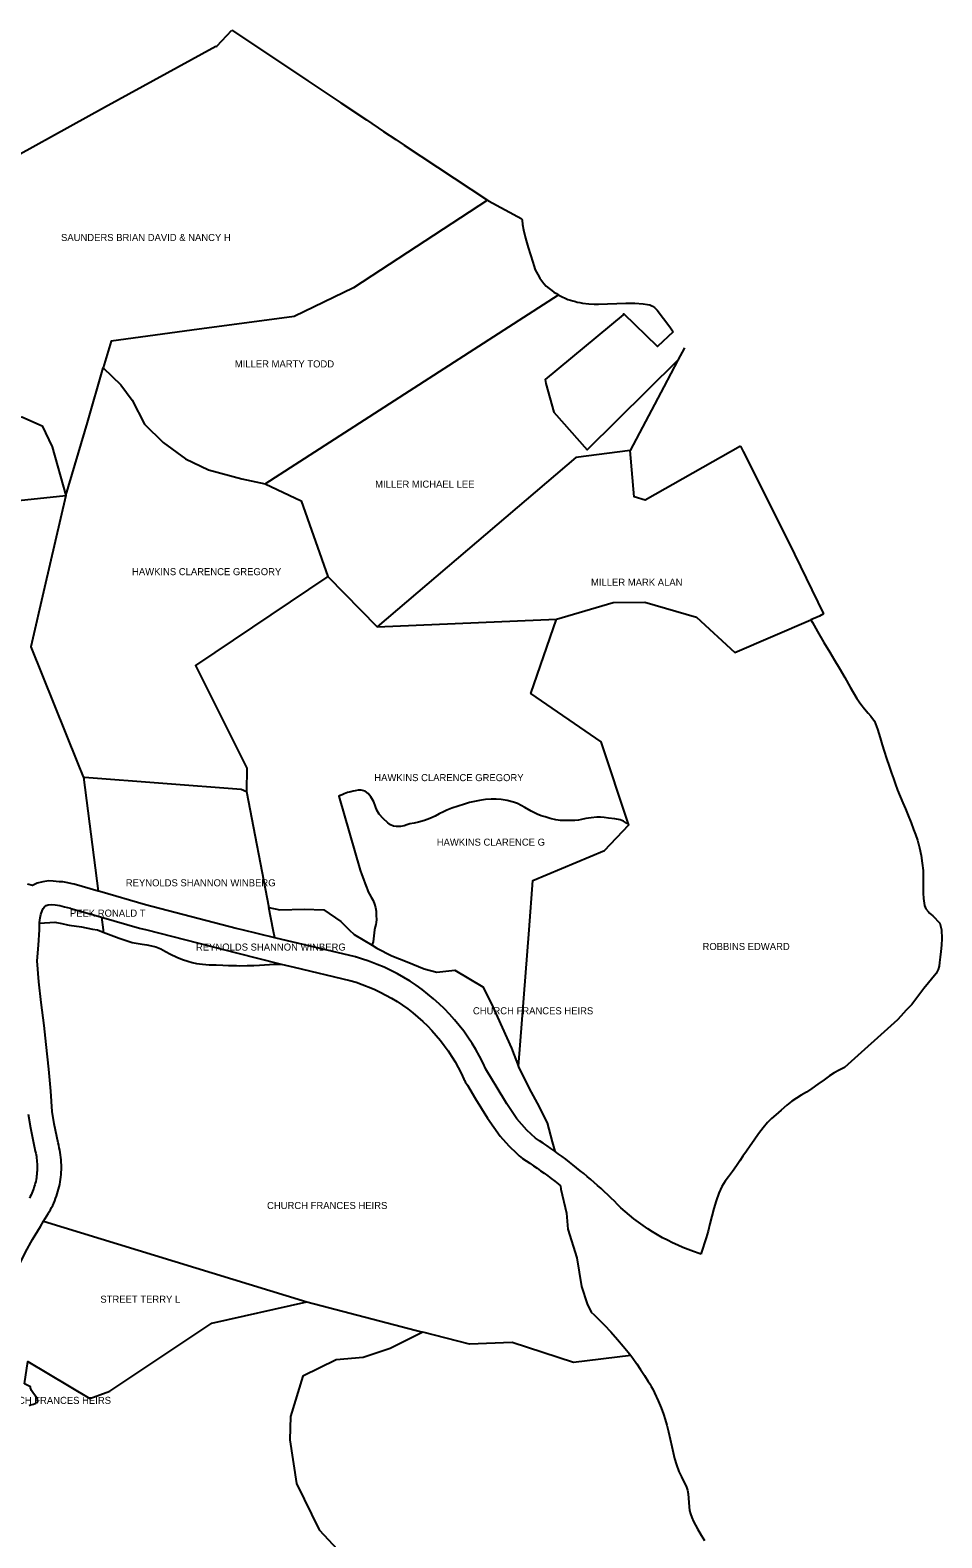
# Model space of a CAD drawing. Extents: x 1249333 to 1254314, y 856599 to 862241.
# Drawn here: x 1252043 to 1254314, y 858486 to 862241 of the extents above; entities that cross this region are included whole.
import ezdxf

# ---------------------------------------------------------------- set-up
doc = ezdxf.new("R2010")
doc.units = 0
doc.layers.add('Old_Level_12', color=7, linetype='Continuous')
doc.layers.add('Old_Level_32', color=7, linetype='Continuous')

msp = doc.modelspace()

# ---------------------------------------------------------------- linework, layer by layer
at = {"layer": 'Old_Level_12'}
for p, q in [((1252545.5, 862241), (1252649, 862172)), ((1252649, 862172), (1252734.875, 862114.813)), ((1252734.875, 862114.813), (1252817.375, 862059.75)), ((1252817.375, 862059.75), (1252881.125, 862017.25)), ((1252628.5, 861110.625), (1253359, 861581.875)), ((1253673, 861449.875), (1253656.75, 861419.125)), ((1253656.75, 861419.125), (1253621.625, 861352.813)), ((1253621.625, 861352.813), (1253537.5, 861193.938)), ((1253812.375, 861204.75), (1253819, 861191.938)), ((1252785, 860880.313), (1252907.625, 860755.063)), ((1252907.625, 860755.063), (1253354.25, 860774.188)), ((1252175.875, 860380.625), (1252212.25, 860096.5)), ((1252582.5, 860344.5), (1252638, 860056)), ((1252664.875, 859915.563), (1252668.5, 859914.625)), ((1254203.25, 859775.813), (1254071.75, 859657.25)), ((1252076.875, 859274.438), (1252732, 859073.375)), ((1252732, 859073.375), (1253021.75, 858998.313))]:
    msp.add_line(p, q, dxfattribs=at)
for points in [[(1252506.125, 862199.875), (1252508.625, 862201.188), (1252545.5, 862241)], [(1252506.125, 862199.875), (1252228.75, 862048.438), (1251924.5, 861880.5), (1251772.125, 861797.75), (1251710.5, 861821.313), (1251641, 861821.313)], [(1252881.125, 862017.25), (1252923.75, 861988.875), (1252954.25, 861968.625)], [(1252954.25, 861968.625), (1252975.25, 861954.75), (1253182.125, 861817.813)], [(1251641, 861821.313), (1251574.25, 861769.375), (1251555.375, 861709.75), (1251720.125, 861462.25), (1251852.5, 861261.125), (1251911.625, 861274.75), (1252022.875, 861277.5), (1252073.25, 861255.125), (1252098, 861203.188), (1252131.875, 861081.875)], [(1253182.125, 861817.813), (1252848.5, 861599), (1252701, 861527.438), (1252446.25, 861493.438), (1252244.75, 861466.688), (1252225.5, 861399.938)], [(1253182.125, 861817.813), (1253185.25, 861815.75), (1253268.25, 861771.188)], [(1253268.25, 861771.188), (1253268.375, 861767.563), (1253269.375, 861757.188), (1253271.875, 861743.625), (1253276.875, 861722.5), (1253283.375, 861699.875), (1253295.25, 861662.938), (1253297.75, 861654.438), (1253301.5, 861643.75), (1253307.375, 861632.188), (1253313, 861623.25), (1253317.875, 861616.313), (1253322.375, 861610.125), (1253328.625, 861603.563), (1253336, 861597.563), (1253342.375, 861592.563), (1253348, 861588.5), (1253354, 861584.75), (1253359, 861581.875)], [(1253359, 861581.875), (1253360.375, 861581.063), (1253368.25, 861577), (1253375.5, 861573.563), (1253382.625, 861570.5), (1253389, 861568.438), (1253395.25, 861566.688), (1253401.25, 861565.125), (1253406, 861563.875), (1253412, 861562.5), (1253419.375, 861561.25), (1253435, 861559.563), (1253447.875, 861558.688), (1253459, 861558.188), (1253526.875, 861560.938), (1253549.5, 861560.938), (1253570, 861559.25), (1253581.25, 861557.438), (1253586.375, 861556.5), (1253593.625, 861553.188), (1253598.5, 861549.875), (1253604.875, 861543.75), (1253636.375, 861501.813), (1253644.875, 861489.688)], [(1253644.875, 861489.688), (1253605.625, 861453.125), (1253521.625, 861534.75), (1253520, 861532.313), (1253326.375, 861371.125), (1253327.875, 861361.125), (1253347.875, 861289.5), (1253430.375, 861195.5), (1253656.75, 861419.125)], [(1252131.875, 861081.875), (1252186.375, 861263.938), (1252225.5, 861399.938)], [(1252225.5, 861399.938), (1252269.25, 861357.875), (1252297, 861319.125), (1252328.375, 861260), (1252374.5, 861213.875), (1252429.875, 861173.25), (1252487.125, 861145.563), (1252570.25, 861123.375), (1252628.5, 861110.625)], [(1253537.5, 861193.938), (1253402.75, 861176.375), (1252907.625, 860755.063)], [(1253812.375, 861204.75), (1253575.125, 861070.063), (1253547.875, 861078.375), (1253537.5, 861193.938)], [(1253819, 861191.938), (1253933.375, 860964.875), (1254019.25, 860787.188)], [(1252628.5, 861110.625), (1252718.125, 861068.375), (1252785, 860880.313)], [(1251142.625, 860976.438), (1251233.125, 860988.438), (1251635.75, 861029.625), (1252131.875, 861081.875)], [(1252131.875, 861081.875), (1252078.875, 860852.5), (1252044.875, 860704.938), (1252160.75, 860415.813), (1252175.5, 860381.25), (1252175.875, 860380.625)], [(1252785, 860880.313), (1252455.125, 860658.813), (1252582.875, 860402.5), (1252582.5, 860344.5)], [(1253354.25, 860774.188), (1253495.125, 860815.063), (1253574.5, 860816.5), (1253703.25, 860779.313)], [(1253533.625, 860263.25), (1253465.125, 860468.25), (1253290, 860589), (1253354.25, 860774.188)], [(1253703.25, 860779.313), (1253798.625, 860691), (1253987.75, 860772.438)], [(1254019.25, 860787.188), (1254009.25, 860781.688), (1253987.75, 860772.438)], [(1253987.75, 860772.438), (1253991.625, 860765.25), (1254004.5, 860742.938), (1254020.375, 860716.125), (1254035.125, 860691.438), (1254046.875, 860672.125), (1254058.25, 860653.125), (1254072.25, 860628.813), (1254086.125, 860604.188), (1254094, 860590.25), (1254102.25, 860576.75), (1254112.5, 860562.188), (1254121.875, 860550.25), (1254130.625, 860539.875), (1254137.625, 860532.625), (1254146.125, 860519.5), (1254153.875, 860499.563), (1254160.5, 860478.25), (1254165.375, 860461.125), (1254170.25, 860444.813), (1254176, 860426.625), (1254182.75, 860407.438), (1254188.875, 860390.25), (1254193.625, 860377.063), (1254198, 860364.563), (1254203.875, 860348.438), (1254210.375, 860331.875), (1254216.875, 860316.5), (1254223.375, 860301.75), (1254230.375, 860285.125), (1254237.5, 860266.875), (1254243.75, 860250.438), (1254248.75, 860237.5), (1254253.5, 860223.125), (1254255.125, 860216.938), (1254255.875, 860214.125)], [(1252175.875, 860380.625), (1252178.625, 860380.5), (1252568.75, 860350.688), (1252582.5, 860344.5)], [(1253533.625, 860263.25), (1253529, 860265.875), (1253521.5, 860270.688), (1253513.25, 860273.938), (1253499.625, 860276.375), (1253483.5, 860278.313), (1253472.75, 860279.625), (1253463.75, 860280.5), (1253454.75, 860280.688), (1253441, 860279.375), (1253427.375, 860277.063), (1253416.75, 860274.688), (1253409.375, 860273.438), (1253399.75, 860272.688), (1253388.75, 860272.313), (1253375.75, 860272.188), (1253364.375, 860272.625), (1253352.75, 860274.313), (1253338.875, 860277.75), (1253325.75, 860281.625), (1253316.375, 860284.313), (1253305.75, 860288.563), (1253291.125, 860296.125), (1253275.625, 860304.688), (1253265.875, 860310.063), (1253256.75, 860314.625), (1253247.125, 860318.313), (1253231.75, 860322.063), (1253216.375, 860324.438), (1253203.625, 860325.875), (1253191.75, 860326), (1253177.25, 860324.563), (1253162.375, 860322.313), (1253149.75, 860319.875), (1253137.75, 860317), (1253125.25, 860313.5), (1253109.125, 860308.438), (1253093.625, 860303.063), (1253081.25, 860298.313), (1253072.625, 860294.313), (1253062.375, 860289), (1253052, 860283.5), (1253038.875, 860277.25), (1253025.375, 860272.188), (1253010.5, 860268.313), (1252999.5, 860266.188), (1252989.125, 860264.063), (1252981.25, 860261.5), (1252974.5, 860259.063), (1252965.5, 860257.375), (1252956.125, 860257.125), (1252948.125, 860258.75), (1252941, 860262), (1252934.125, 860266.688), (1252922.5, 860277.063), (1252912.75, 860288.438), (1252906.875, 860298.313), (1252903.625, 860307.5), (1252898.875, 860319.125), (1252892.125, 860331.063), (1252885.25, 860339.563), (1252877.375, 860345.563), (1252867.75, 860348.25), (1252860.125, 860347.875), (1252853, 860346.563), (1252847.75, 860345.5), (1252841.875, 860344.188), (1252833.875, 860341.813), (1252825, 860338.688), (1252820.125, 860336.688), (1252815.75, 860334.875), (1252811.75, 860333.063), (1252864.875, 860148.75), (1252869.5, 860137), (1252873.25, 860126.5), (1252877.75, 860114.375), (1252880.75, 860106.375), (1252883.375, 860099.438), (1252885.375, 860094.75), (1252888.375, 860089.313), (1252892.875, 860081.563), (1252897.375, 860073.188), (1252901.125, 860064.5), (1252903.625, 860056), (1252904.875, 860046.375), (1252905.5, 860035.875), (1252905.625, 860026.313), (1252905.25, 860018.813), (1252904.375, 860013.75), (1252902.875, 860007.25), (1252901.25, 860000.375), (1252897.625, 859970.188), (1252895.5, 859963.625), (1252894.875, 859961.75)], [(1253259.625, 859659.375), (1253286.375, 860000), (1253295.625, 860123.188), (1253474.25, 860197.938), (1253534.25, 860261.5), (1253533.625, 860263.25)], [(1254255.875, 860214.125), (1254258.25, 860204.5), (1254262.375, 860185.125), (1254265.5, 860166.125), (1254267.25, 860147.625), (1254268, 860126.75), (1254267.75, 860108.125), (1254267.5, 860091.375), (1254268.375, 860078), (1254270.75, 860060.938), (1254274.5, 860052.688), (1254280.75, 860044.875), (1254283.75, 860042.063)], [(1252212.25, 860096.5), (1252153, 860113.625), (1252148, 860114.813), (1252137.25, 860117.313), (1252124.5, 860119.438), (1252115.625, 860120), (1252100.25, 860121.563), (1252089.375, 860121.875), (1252075.125, 860120.125), (1252060.875, 860116.25), (1252049.375, 860110.813), (1252036.625, 860114.063)], [(1252652.375, 859980.625), (1252571.5, 860000), (1252556.75, 860003.813), (1252330.625, 860062.25), (1252216.375, 860095.313), (1252212.25, 860096.5)], [(1252066.625, 860016.75), (1252066.625, 860018.375), (1252067.125, 860024.5), (1252068.125, 860030.438), (1252069.75, 860038.375), (1252072.75, 860047.313), (1252075.5, 860053.625), (1252078.875, 860057.375), (1252083.125, 860060.5), (1252088.125, 860062.063), (1252096.625, 860063.125), (1252105.125, 860062.625), (1252117, 860060.5), (1252129, 860057.375), (1252143.5, 860053.938), (1252144.75, 860053.625), (1252212.875, 860033.875), (1252220.625, 860031.625)], [(1252220.625, 860031.625), (1252224.75, 860000), (1252225.375, 859994.375)], [(1252220.625, 860031.625), (1252315.625, 860004.125), (1252333.875, 860000), (1252556.875, 859943.063), (1252664.875, 859915.563)], [(1252652.375, 859980.625), (1252648.75, 860000), (1252638, 860056)], [(1252638, 860056), (1252665.25, 860049.688), (1252726, 860051.875), (1252774.875, 860050.125), (1252816.75, 860021.125), (1252838.25, 860000), (1252850.25, 859988.188), (1252894.875, 859961.75)], [(1254283.75, 860042.063), (1254291.625, 860034.688), (1254309.25, 860016.75), (1254313.25, 860000), (1254314.125, 859978.313), (1254313.5, 859961.75), (1254312, 859946.5), (1254310, 859931.75), (1254308.125, 859918.875), (1254307.125, 859909.375), (1254305, 859901.313), (1254299.875, 859891), (1254269.25, 859853.688), (1254239.5, 859814.188), (1254225.625, 859799.688), (1254211.625, 859784.875), (1254203.25, 859775.813)], [(1252076.875, 859274.438), (1252089, 859294.875), (1252090.75, 859297.688), (1252093.75, 859303), (1252096.625, 859308.438), (1252099.375, 859313.938), (1252102, 859319.5), (1252104.375, 859325.125), (1252106.625, 859330.813), (1252108.75, 859336.563), (1252110.75, 859342.375), (1252112.5, 859348.25), (1252114.125, 859354.188), (1252115.625, 859360.125), (1252116.875, 859366.125), (1252118, 859372.188), (1252119, 859378.25), (1252119.75, 859384.313), (1252120.375, 859390.438), (1252120.75, 859396.563), (1252121, 859402.688), (1252121.125, 859408.813), (1252121, 859414.938), (1252120.75, 859421.063), (1252120.375, 859427.188), (1252119.75, 859433.313), (1252119, 859439.375), (1252118.125, 859445.438), (1252117, 859451.5), (1252115.75, 859457.5), (1252114.25, 859463.438), (1252112.625, 859469.375), (1252102.75, 859517.375), (1252098.375, 859547.563), (1252094.375, 859598.25), (1252089.625, 859653.188), (1252082.75, 859714.188), (1252077.875, 859761.563), (1252070.625, 859819), (1252064.75, 859870.563), (1252061, 859922.625), (1252063.625, 859961.938), (1252066.875, 860000), (1252066.75, 860012.063), (1252066.625, 860016.75)], [(1252066.625, 860016.75), (1252104.75, 860019.125), (1252121.75, 860015.813), (1252136.25, 860012.438), (1252140.375, 860011.875), (1252171.5, 860007.438), (1252198.625, 860002.125), (1252211, 860000), (1252225.375, 859994.375)], [(1252225.375, 859994.375), (1252264.875, 859979), (1252282.25, 859973.25), (1252297.5, 859968.813), (1252312.125, 859965.75), (1252322.375, 859964.313), (1252333.75, 859962.688), (1252345.5, 859960.625), (1252356.5, 859957.75), (1252368.875, 859952.688), (1252380.5, 859946.375), (1252393.125, 859939.375), (1252408.5, 859932.188), (1252422.875, 859926.5), (1252435.625, 859922), (1252447, 859918.625), (1252457.625, 859916.188), (1252472.25, 859914.25), (1252488.875, 859913.25), (1252506.25, 859912.625), (1252522.875, 859912.188), (1252537, 859911.625), (1252550.75, 859911.063), (1252557, 859910.938)], [(1253350, 859448.5), (1253340.125, 859455.5), (1253330.75, 859462), (1253321.25, 859468.438), (1253311.75, 859474.813), (1253302.125, 859481.063), (1253280.625, 859501.063), (1253255.75, 859529.625), (1253230.75, 859566.688), (1253204, 859610.563), (1253194.875, 859625.563), (1253178.5, 859652.813), (1253170.75, 859669.438), (1253162.375, 859685.75), (1253153.375, 859701.75), (1253143.875, 859717.438), (1253133.75, 859732.75), (1253123.125, 859747.688), (1253111.875, 859762.25), (1253100.125, 859776.375), (1253087.875, 859790.063), (1253075.125, 859803.313), (1253061.875, 859816.063), (1253048.25, 859828.313), (1253034.125, 859840.063), (1253019.625, 859851.313), (1253004.75, 859862), (1252989.5, 859872.125), (1252973.875, 859881.688), (1252957.875, 859890.688), (1252941.5, 859899.125), (1252924.875, 859906.938), (1252908, 859914.125), (1252890.875, 859920.688), (1252881.75, 859923.813), (1252873.5, 859926.625), (1252855.875, 859931.938), (1252855.375, 859932.125), (1252853.375, 859932.563), (1252652.375, 859980.625)], [(1252894.875, 859961.75), (1252906.625, 859954.813), (1252943.75, 859935.5), (1252982.125, 859920.563), (1253024.375, 859902.813), (1253056, 859895.063), (1253101.25, 859899.75), (1253170.75, 859858.25), (1253191.75, 859817.375), (1253218.75, 859757.25), (1253242.25, 859705.125), (1253259.625, 859659.375)], [(1252557, 859910.938), (1252565.875, 859910.75), (1252583.625, 859911), (1252600.25, 859911.625), (1252614.375, 859912.375), (1252627.125, 859913.25), (1252639.625, 859914.188), (1252651.25, 859914.813), (1252663.625, 859914.938), (1252665, 859914.875), (1252668.5, 859914.625)], [(1252668.5, 859914.625), (1252701.25, 859906.875), (1252839.625, 859874.188), (1252855.125, 859869.5), (1252870.375, 859864.25), (1252881.125, 859860.125), (1252885.5, 859858.438), (1252900.375, 859852.125), (1252915, 859845.25), (1252929.375, 859837.813), (1252943.5, 859829.875), (1252957.25, 859821.438), (1252970.75, 859812.5), (1252983.875, 859803.063), (1252996.625, 859793.188), (1253009, 859782.813), (1253021, 859772), (1253032.625, 859760.75), (1253043.875, 859749.125), (1253054.625, 859737.063), (1253065, 859724.625), (1253074.875, 859711.813), (1253084.25, 859698.688), (1253093.125, 859685.188), (1253101.5, 859671.375), (1253109.375, 859657.25), (1253116.75, 859642.875), (1253123.625, 859628.25), (1253125, 859625.313), (1253127.125, 859621.813), (1253132.375, 859613.188), (1253152.75, 859579.438), (1253182, 859531.313), (1253214.125, 859485.875), (1253235.625, 859462.063), (1253255.625, 859443.313), (1253261.5, 859437.563), (1253269.625, 859430.688), (1253278.75, 859424.75), (1253287.875, 859418.688), (1253296.875, 859412.563), (1253305.875, 859406.375), (1253314.75, 859400.063), (1253323.625, 859393.688), (1253332.375, 859387.25), (1253341.125, 859380.75), (1253349.75, 859374.125), (1253358.375, 859367.438), (1253364, 859362.938)], [(1253259.625, 859659.375), (1253259.625, 859658.75), (1253285.875, 859604.938), (1253306.25, 859568.438), (1253331.25, 859519.125), (1253343.5, 859472.25), (1253350, 859448.5)], [(1254071.75, 859657.25), (1254058.5, 859650.563), (1254045.625, 859643.813), (1254034.375, 859636.563), (1254020.75, 859626.688), (1254005.625, 859615.625), (1253990, 859604.563), (1253976.75, 859596), (1253964, 859588.125), (1253951.875, 859580.688), (1253940.75, 859573.375), (1253927.625, 859563.313), (1253913.625, 859551.375), (1253900.5, 859539.625), (1253890, 859530.188), (1253880.25, 859520.25), (1253869.25, 859507.063), (1253857.75, 859491.938), (1253846.375, 859476.188), (1253836.5, 859462.313), (1253827.375, 859449), (1253818.75, 859436.375), (1253810.75, 859424.625), (1253802.25, 859412.188), (1253792.625, 859398.5), (1253783, 859385.25), (1253774.75, 859374.188), (1253766.5, 859360.813), (1253759, 859344.188), (1253752.25, 859325.5), (1253746.375, 859306.188), (1253741.125, 859286.75), (1253736.5, 859268.063), (1253731.75, 859250), (1253726.75, 859232.625), (1253722.875, 859220.375), (1253718.625, 859207.25), (1253715, 859194.688), (1253714.5, 859192.75)], [(1252038.625, 859540.813), (1252043.75, 859507), (1252053.875, 859457.375), (1252054.5, 859454), (1252054.875, 859452.813), (1252056, 859448.5), (1252057, 859444.188), (1252057.875, 859439.813), (1252058.625, 859435.438), (1252059.25, 859431.063), (1252059.75, 859426.625), (1252060.125, 859422.188), (1252060.375, 859417.75), (1252060.5, 859413.313), (1252060.5, 859404.438), (1252060.375, 859400), (1252060.125, 859395.563), (1252059.75, 859391.125), (1252059.25, 859386.688), (1252058.625, 859382.313), (1252057.875, 859377.938), (1252057, 859373.563), (1252056, 859369.25), (1252054.875, 859364.938), (1252053.625, 859360.688), (1252052.25, 859356.438), (1252050.75, 859352.25), (1252049.125, 859348.125), (1252047.375, 859344), (1252045.5, 859339.938), (1252043.5, 859335.938), (1252041.375, 859332)], [(1253714.5, 859192.75), (1253709.25, 859194.375), (1253695.75, 859198.875), (1253682.375, 859203.75), (1253669.125, 859209), (1253656.125, 859214.563), (1253643.25, 859220.5), (1253630.5, 859226.813), (1253618, 859233.438), (1253605.625, 859240.438), (1253593.5, 859247.75), (1253581.5, 859255.375), (1253569.75, 859263.375), (1253558.25, 859271.688), (1253547, 859280.313), (1253536, 859289.25), (1253525.25, 859298.438), (1253514.75, 859307.938), (1253506.625, 859316.063), (1253498.5, 859324.125), (1253490.25, 859332.063), (1253482, 859339.938), (1253473.625, 859347.75), (1253465.25, 859355.5), (1253456.75, 859363.188), (1253448.125, 859370.75), (1253439.5, 859378.25), (1253430.75, 859385.688), (1253422, 859393.063), (1253413.125, 859400.313), (1253404.25, 859407.5), (1253395.25, 859414.625), (1253386.25, 859421.625), (1253377.125, 859428.563), (1253368, 859435.438), (1253358.75, 859442.188), (1253350, 859448.5)], [(1253364, 859362.938), (1253365.125, 859354.563), (1253379.375, 859294.563), (1253382.375, 859254.688), (1253405.125, 859183.125), (1253416.5, 859111.75), (1253430.875, 859068.875), (1253440.25, 859048.125), (1253448.375, 859040.938), (1253460.875, 859029.188), (1253474.125, 859015.688), (1253489.25, 858999), (1253506.25, 858979.563), (1253520.75, 858962.938), (1253533.125, 858948), (1253539.25, 858940.125)], [(1251864.75, 858925.188), (1251873, 858939.75), (1251930.125, 859012.125), (1251968.875, 859075.25), (1251991.375, 859115.063), (1252031.875, 859197), (1252049.25, 859229.188), (1252068.875, 859261.063), (1252076.875, 859274.438)], [(1252028.875, 858869.563), (1252037.125, 858924.688), (1252192.25, 858832.625), (1252241.625, 858851.188), (1252496.125, 859020.25), (1252732, 859073.375)], [(1253021.75, 858998.313), (1252940, 858957.438), (1252872.875, 858935), (1252805.625, 858929), (1252722.375, 858888.5), (1252691.625, 858787.813), (1252690, 858729.813), (1252706.5, 858621.438), (1252763.25, 858505.438), (1252808.5, 858456.688), (1252801.25, 858395.875), (1252713.625, 858265.5), (1252688.5, 858083.875), (1252630.5, 857884.25)], [(1253539.25, 858940.125), (1253396.375, 858922.625), (1253243.625, 858972.25), (1253137.75, 858968.25), (1253021.75, 858998.313)], [(1253539.25, 858940.125), (1253544.375, 858933.438), (1253553.75, 858920.188), (1253554.25, 858919.438)], [(1253554.25, 858919.438), (1253563.75, 858905.25), (1253573.625, 858889.938), (1253582.75, 858875.438), (1253586.625, 858869.25), (1253590.375, 858862.875), (1253594.25, 858855.688), (1253598.375, 858847.063), (1253607.25, 858827.063), (1253614.625, 858809.313), (1253620.625, 858793.875), (1253625.25, 858780.625), (1253629.375, 858766.75), (1253633.625, 858749.813), (1253637.75, 858731.438), (1253641.625, 858713.438), (1253644.875, 858698), (1253648.375, 858683.25), (1253652.875, 858668), (1253659.25, 858651.063), (1253665.5, 858637.438), (1253671.625, 858625.25), (1253677, 858614.313), (1253680.75, 858604.25), (1253682.5, 858595.313), (1253683.375, 858584.875), (1253684, 858573.813), (1253684.75, 858563.063), (1253685.875, 858554), (1253687.875, 858545.375), (1253691, 858536.375), (1253695.625, 858526.25), (1253705.25, 858508.313), (1253714.625, 858492.563), (1253723.125, 858479.375)], [(1252040.5, 858815.813), (1252044.375, 858817.125), (1252048.125, 858817.938), (1252051.875, 858818.813), (1252055.75, 858820.25), (1252057.75, 858821.375), (1252059.625, 858822.688), (1252061.25, 858824.063), (1252062.125, 858825.438), (1252061.625, 858831.063), (1252057.5, 858837.688), (1252051.75, 858844.938), (1252046.875, 858852.625), (1252044.5, 858859.813), (1252044.25, 858862.25), (1252028.875, 858869.563)]]:
    msp.add_lwpolyline(points, dxfattribs=at)

# ---------------------------------------------------------------- texts
at = {"layer": 'Old_Level_32'}
for s, p in [('SAUNDERS BRIAN DAVID & NANCY H', (1252120.125, 861715.813)), ('MILLER MARTY TODD', (1252553, 861400.938)), ('MILLER MICHAEL LEE', (1252902.5, 861101.5)), ('HAWKINS CLARENCE GREGORY', (1252297, 860883.5)), ('MILLER MARK ALAN', (1253440.25, 860857.125)), ('HAWKINS CLARENCE GREGORY', (1252900.5, 860370.5)), ('HAWKINS CLARENCE G', (1253056, 860209.75)), ('REYNOLDS SHANNON WINBERG', (1252281.5, 860108.5)), ('PEEK RONALD T', (1252142.25, 860033)), ('REYNOLDS SHANNON WINBERG', (1252456.25, 859948.438)), ('ROBBINS EDWARD', (1253718, 859949.938)), ('CHURCH FRANCES HEIRS', (1253146.125, 859789.75)), ('CHURCH FRANCES HEIRS', (1252633.25, 859304.813)), ('STREET TERRY L', (1252218.125, 859071.375)), ('CHURCH FRANCES HEIRS', (1251944.875, 858819.375))]:
    msp.add_text(s, height=17.61477, dxfattribs=at).set_placement(p)

doc.saveas('drawing.dxf')
